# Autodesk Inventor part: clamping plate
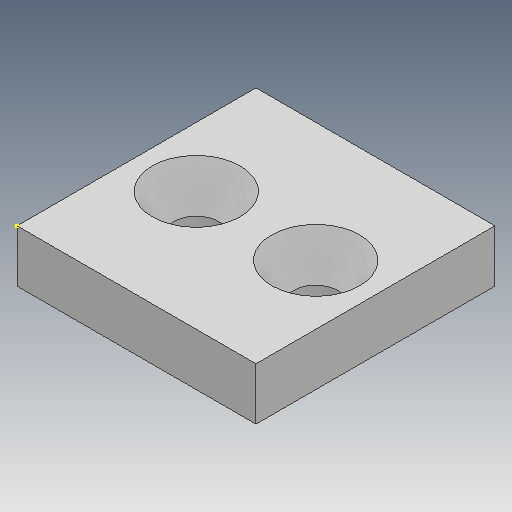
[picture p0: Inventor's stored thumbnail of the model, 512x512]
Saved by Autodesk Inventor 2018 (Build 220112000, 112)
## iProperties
Created: 2016-03
Part Number: clamping plate
Material: Generic
Document SubType Name: Modeling
Designer: Sandeep
Density: 1 g/cm^3
Appearance: Default
Mass: 6.41192 g
Surface Area: 30.6752 cm^2
Volume: 6.41192 cm^3
Author: Sandeep
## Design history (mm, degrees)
sketch "Sketch1"
  geometry: L1 (0, 0)-(32, 0); L2 (32, 0)-(32, 32); L3 (32, 32)-(0, 32); L4 (0, 32)-(0, 0)
  constraints: 8 end point, 2 parallel, 1 horizontal, 1 perpendicular
  dimensions: "d0" = 32 distance between parallel lines of L1 L3; "d1" = 32 distance of L2.end L3.end
extrude "Extrusion1" new body sketch "Sketch1" distance "d2" = 7; taper "d3" = 0 deg
sketch "Sketch2"
  geometry: 1 further point
sketch "Sketch3"
  geometry: 1 further point
hole "Hole2" diameter "d15" = 6; stored, may be unused: countersink angle "d19" = 60 deg, drill point angle "d21" = 118 deg; dims "d13" = 8, "d14" = 16, "d16" = 6, "d17" = 11.78, "d18" = 2, "d20" = 8
sketch "Sketch4"
  geometry: 1 further point
hole "Hole3" diameter "d24" = 6; stored, may be unused: countersink angle "d28" = 60 deg, drill point angle "d30" = 118 deg; dims "d22" = 8, "d23" = 16, "d25" = 6, "d26" = 11.78, "d27" = 2, "d29" = 8
body "Solid1"
